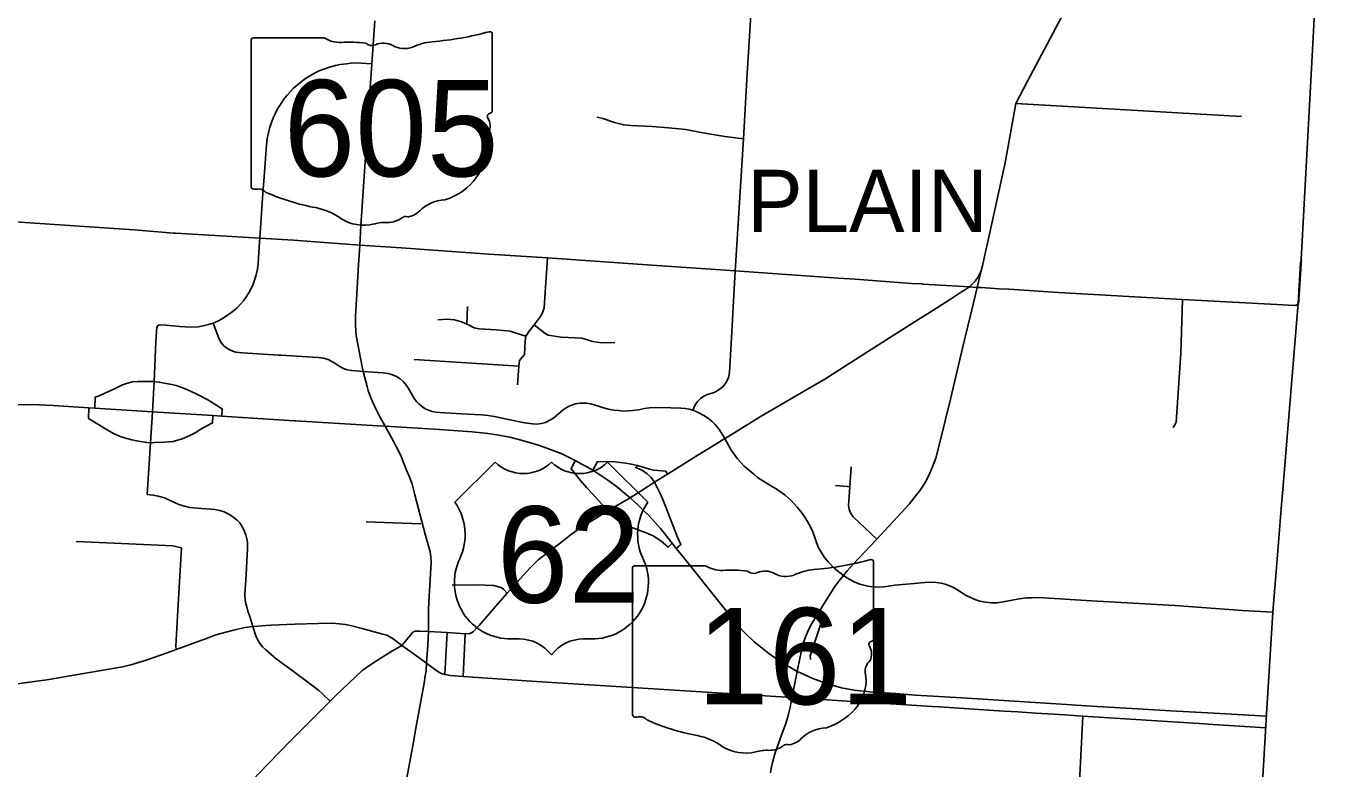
# Model space of a CAD drawing. Extents: x 1755200 to 1902939, y 644115 to 788070.
# Drawn here: x 1876290 to 1895161, y 756753 to 767475 of the extents above; entities that cross this region are included whole.
import ezdxf

# ---------------------------------------------------------------- set-up
doc = ezdxf.new("R2010")
doc.units = 0
for name, color, linetype in [('GM_X_City_Street', 7, 'Continuous'), ('GM_X_County', 7, 'Continuous'), ('GM_X_County_Road', 7, 'Continuous'), ('GM_X_Interchange_Ramps', 7, 'Continuous'), ('GM_X_State_Route', 7, 'Continuous'), ('GM_X_State_Shield', 7, 'Continuous'), ('GM_X_Township_Road', 7, 'Continuous'), ('GM_X_Township_Text', 7, 'Continuous'), ('GM_X_US_Route', 7, 'Continuous'), ('GM_X_US_Shield', 7, 'Continuous')]:
    doc.layers.add(name, color=color, linetype=linetype)

msp = doc.modelspace()

# ---------------------------------------------------------------- linework, layer by layer
at = {"layer": 'GM_X_City_Street'}
for points in [[(1879665, 764416), (1879710, 765065), (1879729, 765301), (1879750, 765625), (1879761, 765760), (1879771, 765853), (1879788, 765933), (1879805, 766001), (1879835, 766086), (1879859, 766149), (1879892, 766220), (1879921, 766279), (1879962, 766346), (1880013, 766422), (1880059, 766478), (1880153, 766579), (1880231, 766649), (1880311, 766710), (1880387, 766760), (1880463, 766799), (1880524, 766828), (1880587, 766854), (1880672, 766884), (1880760, 766907), (1880826, 766921), (1880916, 766932), (1880978, 766939), (1881052, 766943), (1881281, 766929)], [(1886648, 765849), (1886648, 765849), (1886705, 766792)], [(1884537, 766160), (1884616, 766141), (1884785, 766084), (1884921, 766050), (1885023, 766039), (1885329, 766028), (1885566, 766005), (1885815, 765982), (1886064, 765937), (1886381, 765880), (1886648, 765849)], [(1886535, 764015), (1886648, 765849)], [(1875732, 764675), (1875910, 764665), (1877850, 764535), (1878419, 764488), (1878447, 764486)], [(1878447, 764486), (1879014, 764455), (1879665, 764416), (1880151, 764384), (1881111, 764314)], [(1878163, 762916), (1878174, 763071), (1878179, 763120), (1878188, 763150), (1878212, 763161), (1878309, 763158), (1878510, 763141), (1878589, 763133), (1878681, 763130), (1878773, 763136), (1878847, 763151), (1878925, 763167), (1878990, 763189), (1879067, 763222), (1879152, 763267), (1879262, 763344), (1879339, 763408), (1879385, 763461), (1879429, 763511), (1879473, 763570), (1879511, 763634), (1879563, 763735), (1879595, 763822), (1879613, 763886), (1879631, 763969), (1879641, 764050), (1879661, 764362)], [(1879661, 764362), (1879665, 764416)], [(1881111, 764314), (1881704, 764273), (1882972, 764185), (1883819, 764131), (1885188, 764036), (1886531, 763943), (1888019, 763839), (1888260, 763821), (1888327, 763816)], [(1883388, 762296), (1883407, 762564), (1883413, 762646), (1883485, 762737), (1883495, 762929), (1883506, 763001), (1883554, 763074), (1883625, 763162), (1883727, 763297), (1883754, 763352), (1883770, 763410), (1883786, 763630), (1883819, 764131)], [(1885918, 761930), (1885950, 762007), (1885986, 762058), (1886028, 762100), (1886076, 762133), (1886132, 762158), (1886227, 762188), (1886285, 762218), (1886350, 762269), (1886400, 762333), (1886433, 762402), (1886448, 762475), (1886480, 763064), (1886531, 763943), (1886535, 764015)], [(1888317, 759797), (1888574, 760070), (1889041, 760575), (1889145, 760702), (1889193, 760763), (1889266, 760875), (1889320, 760977), (1889350, 761047), (1889381, 761113), (1889426, 761236), (1889486, 761464), (1889640, 762089), (1889813, 762827), (1889891, 763144), (1889947, 763382), (1890022, 763700)], [(1890022, 763700), (1890022, 763700), (1890087, 763700), (1890335, 763685)], [(1890335, 763685), (1890482, 763677), (1891197, 763632), (1892213, 763572)], [(1892853, 761682), (1892880, 761718), (1892897, 761759), (1892963, 762753), (1892991, 763528)], [(1882654, 763172), (1882663, 763430)], [(1878990, 763189), (1879042, 763047), (1879067, 762978), (1879088, 762936), (1879116, 762893), (1879150, 762856), (1879201, 762818), (1879242, 762796), (1879277, 762781), (1879318, 762769), (1879365, 762763), (1879414, 762760), (1879935, 762727), (1879968, 762725)], [(1882236, 763236), (1882368, 763246), (1882474, 763235), (1882575, 763205), (1882654, 763172), (1882679, 763162), (1882758, 763119), (1882834, 763104), (1883078, 763090), (1883282, 763071), (1883353, 763049), (1883506, 763001)], [(1883625, 763162), (1883787, 763038), (1883829, 763012), (1884019, 762985), (1884317, 762969), (1884364, 762956), (1884476, 762921), (1884598, 762901), (1884790, 762906)], [(1878138, 762343), (1878163, 762916)], [(1879968, 762725), (1880507, 762691), (1880546, 762687), (1880585, 762680), (1880617, 762671), (1880660, 762658), (1880686, 762644), (1880726, 762622), (1880821, 762562), (1880862, 762539), (1880895, 762525), (1880932, 762513), (1880992, 762502), (1881159, 762491), (1881448, 762470), (1881517, 762460), (1881579, 762441), (1881637, 762416), (1881691, 762384), (1881736, 762345), (1881784, 762289), (1881814, 762246), (1881846, 762184), (1881875, 762133), (1881905, 762086), (1881932, 762051), (1881967, 762016), (1882014, 761977), (1882053, 761952), (1882101, 761932), (1882156, 761912), (1882213, 761901), (1882265, 761897), (1882579, 761878), (1882864, 761862), (1882963, 761854), (1883055, 761839), (1883258, 761798), (1883492, 761750), (1883605, 761732), (1883665, 761731), (1883732, 761739), (1883790, 761755), (1883855, 761785), (1883904, 761815), (1883984, 761884), (1884044, 761934), (1884089, 761966), (1884134, 761989), (1884180, 762008), (1884230, 762021), (1884283, 762030), (1884345, 762034), (1884389, 762031), (1884440, 762024), (1884495, 762009), (1884599, 761974), (1884694, 761947), (1884775, 761933), (1884847, 761925), (1884906, 761919), (1884985, 761920), (1885053, 761926), (1885133, 761938), (1885222, 761954), (1885294, 761964), (1885381, 761969), (1885598, 761964), (1885747, 761960), (1885811, 761956), (1885864, 761946), (1885918, 761930), (1886007, 761891), (1886076, 761853), (1886131, 761820), (1886194, 761772), (1886242, 761724), (1886305, 761647), (1886379, 761520)], [(1881895, 762665), (1883407, 762564)], [(1878084, 761462), (1878113, 761906), (1878138, 762343)], [(1878036, 760713), (1878084, 761462)], [(1886379, 761520), (1886466, 761361), (1886562, 761229), (1886661, 761121), (1886797, 761005), (1886851, 760958), (1887030, 760848), (1887138, 760784), (1887251, 760702), (1887340, 760625), (1887427, 760531), (1887478, 760466), (1887525, 760400), (1887576, 760322), (1887620, 760238), (1887649, 760175), (1887729, 759955), (1887770, 759881), (1887821, 759805), (1887872, 759740), (1887966, 759647), (1888092, 759545)], [(1888203, 761114), (1888183, 760823), (1888168, 760556), (1888174, 760498), (1888194, 760449), (1888233, 760391), (1888574, 760070)], [(1879471, 759112), (1879464, 759135), (1879453, 759190), (1879449, 759274), (1879466, 759560), (1879487, 759936), (1879487, 760024), (1879479, 760075), (1879465, 760133), (1879436, 760206), (1879406, 760259), (1879375, 760304), (1879342, 760340), (1879295, 760379), (1879227, 760427), (1879150, 760462), (1879086, 760482), (1879013, 760497), (1878766, 760517), (1878651, 760525), (1878576, 760544), (1878493, 760570), (1878372, 760627), (1878288, 760665), (1878196, 760691), (1878125, 760704), (1878036, 760713)], [(1887979, 760842), (1888148, 760830), (1888183, 760823)], [(1881203, 760320), (1881991, 760292)], [(1877013, 760036), (1877343, 760021), (1877352, 760021)], [(1877352, 760021), (1878407, 759972), (1878533, 759946)], [(1878456, 758475), (1878452, 758525), (1878482, 759044), (1878533, 759946)], [(1887361, 757846), (1887425, 758159), (1887466, 758371), (1887505, 758547), (1887539, 758646), (1887573, 758725), (1887628, 758837), (1887717, 758980), (1887780, 759088), (1887969, 759385), (1888026, 759461), (1888092, 759545), (1888148, 759613), (1888239, 759714), (1888317, 759797)], [(1888092, 759545), (1888140, 759510), (1888249, 759452), (1888332, 759418), (1888447, 759389), (1888553, 759378), (1888679, 759379), (1888837, 759404), (1889005, 759421), (1889112, 759431), (1889269, 759442), (1889366, 759447), (1889438, 759445), (1889506, 759434), (1889561, 759420), (1889673, 759375), (1889731, 759344), (1889800, 759297), (1889857, 759261), (1889927, 759226), (1890003, 759195), (1890065, 759176), (1890146, 759159), (1890224, 759152), (1890312, 759152), (1890401, 759162), (1890529, 759188), (1890630, 759206), (1890741, 759220), (1890808, 759222), (1890902, 759225), (1890988, 759222), (1891674, 759179), (1892879, 759110), (1893855, 759041), (1894293, 759014)], [(1882444, 759407), (1882804, 759410), (1883040, 759399), (1883148, 759370), (1883183, 759346), (1883236, 759291)], [(1879562, 758807), (1879521, 758953), (1879494, 759029), (1879471, 759112)], [(1878931, 758651), (1879028, 758687), (1879287, 758754), (1879455, 758792), (1879562, 758807), (1879822, 758827), (1880172, 758844)], [(1880681, 757732), (1880558, 757847), (1880515, 757884), (1880434, 757947), (1880113, 758186), (1879902, 758343), (1879745, 758477), (1879703, 758515), (1879665, 758565), (1879629, 758622), (1879606, 758675), (1879562, 758807)], [(1880172, 758844), (1880174, 758844), (1880508, 758852), (1880708, 758856), (1880809, 758848), (1880903, 758837), (1880996, 758816), (1881142, 758779), (1881315, 758732)], [(1875399, 757881), (1875406, 757881), (1875693, 757917), (1876589, 758040), (1877681, 758226), (1877801, 758254), (1878022, 758324), (1878327, 758429), (1878456, 758475), (1878931, 758651)], [(1881315, 758732), (1881441, 758698), (1881497, 758682), (1881531, 758666), (1881589, 758628), (1881629, 758602), (1881691, 758555)], [(1882074, 758277), (1882074, 758277), (1882089, 758537), (1882099, 758734)], [(1882335, 758115), (1882371, 758720)], [(1882602, 758086), (1882630, 758704)], [(1881691, 758555), (1881716, 758535), (1881845, 758441), (1882074, 758277), (1882205, 758177), (1882276, 758134), (1882305, 758123), (1882335, 758115), (1882345, 758113)], [(1881920, 757341), (1882038, 757991), (1882054, 758096), (1882066, 758170), (1882074, 758277)], [(1882345, 758113), (1882389, 758104), (1882414, 758101), (1882602, 758086), (1883515, 758025)], [(1883515, 758025), (1883808, 758006), (1887349, 757783)], [(1887040, 756698), (1887049, 756760), (1887068, 756847), (1887103, 756969), (1887201, 757255), (1887260, 757407), (1887294, 757522), (1887322, 757641), (1887349, 757783), (1887361, 757846)], [(1887349, 757783), (1888438, 757713)], [(1888438, 757713), (1888853, 757687)], [(1888853, 757687), (1889372, 757654)], [(1889476, 757647), (1890410, 757587)], [(1890617, 757574), (1890669, 757571)], [(1890877, 757558), (1891292, 757531)], [(1881755, 756447), (1881874, 757087), (1881920, 757341)]]:
    msp.add_lwpolyline(points, dxfattribs=at)
at = {"layer": 'GM_X_County'}
msp.add_lwpolyline([(1895161, 772565), (1894704, 764108), (1894692, 764059), (1894658, 763478), (1894436, 760788), (1894418, 760567), (1894359, 759837), (1894293, 759014), (1894201, 757542), (1893595, 747153), (1893596, 747130), (1893480, 745419)], dxfattribs=at)
at = {"layer": 'GM_X_County_Road'}
for points in [[(1894613, 763444), (1894625, 763445), (1894638, 763449), (1894648, 763459), (1894657, 763468), (1894663, 763480), (1894667, 763496), (1894671, 763532), (1894702, 764044), (1894704, 764065), (1894710, 764091)], [(1890022, 763700), (1890077, 763927)], [(1888327, 763816), (1889078, 763761), (1889226, 763753)], [(1889226, 763753), (1889240, 763752), (1889913, 763712)], [(1889913, 763712), (1890022, 763700)], [(1892213, 763572), (1892299, 763566), (1892991, 763528), (1894351, 763455), (1894607, 763444), (1894613, 763444)], [(1887619, 758330), (1887615, 758344), (1887613, 758387), (1887777, 758876), (1887779, 758913), (1887771, 758938), (1887751, 758962), (1887717, 758980)], [(1889372, 757654), (1889476, 757647)], [(1890410, 757587), (1890617, 757574)], [(1890669, 757571), (1890877, 757558)], [(1890890, 747320), (1890890, 747323), (1890931, 747885), (1890949, 748370), (1890978, 749335), (1891096, 750643), (1891349, 754421), (1891423, 755633), (1891501, 756560), (1891551, 757514)], [(1891292, 757531), (1891551, 757514), (1893306, 757404), (1893425, 757394), (1893891, 757364)], [(1893891, 757364), (1894191, 757345)]]:
    msp.add_lwpolyline(points, dxfattribs=at)
at = {"layer": 'GM_X_Interchange_Ramps'}
for points in [[(1878138, 762343), (1878066, 762347), (1877903, 762344), (1877828, 762338), (1877739, 762316), (1877683, 762296), (1877556, 762236), (1877436, 762183), (1877347, 762139), (1877285, 762117), (1877284, 761959)], [(1879114, 761846), (1879119, 761952), (1878912, 762080), (1878774, 762152), (1878656, 762208), (1878551, 762252), (1878455, 762286), (1878392, 762303), (1878208, 762336), (1878138, 762343)], [(1877197, 761965), (1877193, 761811), (1877459, 761646), (1877551, 761596), (1877647, 761553), (1877746, 761521), (1877818, 761505), (1877911, 761482), (1878032, 761463), (1878084, 761462)], [(1878084, 761462), (1878144, 761464), (1878288, 761467), (1878415, 761480), (1878544, 761519), (1878652, 761564), (1878729, 761606), (1878811, 761657), (1878898, 761705), (1878982, 761748), (1878987, 761854)], [(1884220, 761207), (1884160, 761084), (1884202, 761029), (1884294, 760916), (1884389, 760808), (1884465, 760727), (1884647, 760528), (1884681, 760472)], [(1885553, 761009), (1885527, 761051), (1885412, 761058), (1885348, 761066), (1885290, 761081), (1885215, 761102), (1885117, 761134), (1885029, 761153), (1884951, 761167), (1884868, 761177), (1884790, 761183), (1884540, 761188), (1884472, 761066)], [(1885363, 760891), (1885318, 760961), (1885257, 761011), (1885191, 761058), (1885093, 761103), (1885117, 761134)], [(1885678, 759935), (1885745, 759990), (1885695, 760098), (1885484, 760640), (1885448, 760729), (1885383, 760855), (1885363, 760891)], [(1884681, 760472), (1884711, 760433), (1884765, 760394), (1884851, 760331), (1884936, 760283), (1885028, 760241), (1885245, 760161), (1885344, 760115), (1885456, 760044), (1885563, 759955), (1885618, 760010)]]:
    msp.add_lwpolyline(points, dxfattribs=at)
at = {"layer": 'GM_X_State_Route'}
for points in [[(1881111, 764314), (1881125, 764593), (1881150, 764948), (1881252, 766514), (1881281, 766929), (1881324, 767554)], [(1881087, 763959), (1881111, 764314)], [(1881057, 763452), (1881067, 763610), (1881086, 763947), (1881087, 763959)], [(1881475, 761698), (1881405, 761826), (1881342, 761950), (1881270, 762108), (1881231, 762216), (1881213, 762273), (1881159, 762491), (1881142, 762556), (1881057, 763011), (1881051, 763075), (1881045, 763164), (1881047, 763288), (1881057, 763452)], [(1874034, 761315), (1874400, 761488), (1874766, 761657), (1874922, 761724), (1875108, 761792), (1875262, 761840), (1875473, 761897), (1875610, 761930), (1875791, 761963), (1875997, 761991), (1876175, 762006), (1876381, 762012), (1876681, 761999), (1877197, 761965), (1877284, 761959), (1878113, 761906), (1878987, 761854), (1879114, 761846), (1880163, 761777)], [(1880163, 761777), (1880182, 761776), (1881370, 761704)], [(1881370, 761704), (1881475, 761698), (1882262, 761651), (1882733, 761619), (1882960, 761595), (1883087, 761577), (1883275, 761541), (1883458, 761495), (1883706, 761420), (1884019, 761304), (1884220, 761207), (1884472, 761066), (1884704, 760912), (1884834, 760815), (1884933, 760734)], [(1881904, 760707), (1881863, 760863), (1881831, 760952), (1881785, 761066), (1881696, 761287), (1881574, 761517), (1881475, 761698)], [(1882133, 759816), (1882127, 759886), (1882057, 760124), (1881904, 760707)], [(1884933, 760734), (1885012, 760668), (1885130, 760561), (1885221, 760466), (1885286, 760404), (1885452, 760222), (1885618, 760010), (1885678, 759935), (1885754, 759843), (1886364, 759080), (1886567, 758825), (1886685, 758701), (1886799, 758594), (1887014, 758420), (1887181, 758302), (1887425, 758159)], [(1882107, 759167), (1882118, 759401), (1882140, 759736), (1882133, 759816)], [(1882099, 758734), (1882101, 759040), (1882107, 759167)], [(1887425, 758159), (1887473, 758138)], [(1887473, 758138), (1887652, 758059), (1887835, 757991), (1888067, 757925), (1888249, 757891), (1888476, 757865), (1888849, 757839)], [(1888849, 757839), (1889133, 757819), (1889803, 757778), (1891315, 757680)], [(1891315, 757680), (1891524, 757667)], [(1891524, 757667), (1891758, 757652), (1892259, 757623)], [(1892259, 757623), (1892339, 757618), (1892821, 757591), (1893440, 757556), (1894201, 757515)]]:
    msp.add_lwpolyline(points, dxfattribs=at)
at = {"layer": 'GM_X_State_Shield'}
for p, q in [((1880593, 767307), (1879574, 767307)), ((1883020, 766254), (1883020, 767359)), ((1879540, 767270), (1879540, 765157)), ((1883020, 766254), (1883020, 766254)), ((1888529, 758633), (1888529, 759738)), ((1885049, 759650), (1885049, 757536)), ((1886102, 759686), (1885083, 759686)), ((1888529, 758633), (1888529, 758633))]:
    msp.add_line(p, q, dxfattribs=at)
for centre, major_axis, start_param, end_param in [((1879580, 767275), (40.3, 0), 1.712693, 3.28349), ((1880836, 767552), (391, 0), 4.042523, 4.731795), ((1881780, 770188), (3691, 0), 4.814394, 5.042369), ((1882982, 767364), (38.7, 0), 6.141152, 7.989035), ((1880966, 766120), (1404, 0), 1.404758, 1.657858), ((1881284, 767286), (113, 0), 3.836095, 5.185415), ((1881450, 767042), (235, 0), 0.950623, 2.079405), ((1881753, 767377), (282, 0), 4.081561, 5.145723), ((1882251, 766661), (743, 0), 1.699011, 2.107814), ((1883011, 766173), (60, 0), 1.883978, 3.671073), ((1882630, 766033), (360, 0), 5.934695, 6.695948), ((1882979, 766249), (41.5, 0), 5.05454, 6.418171), ((1883159, 765791), (262, 0), 2.387724, 3.262537), ((1881987, 765650), (923, 0), 5.101752, 6.440018), ((1879580, 765153), (40.7, 0), 3.00124, 4.508301), ((1879586, 765369), (310, 0), 4.665946, 4.897461), ((1879650, 765035), (112, 0), 0.519207, 1.627899), ((1881063, 766934), (2665, 0), 4.195997, 4.488961), ((1880268, 764208), (834, 0), 0.823519, 1.323587), ((1882376, 764564), (506, 0), 1.647645, 2.488434), ((1881170, 765025), (529, 0), 4.026481, 4.996735), ((1881476, 764294), (435, 0), 1.495662, 1.94098), ((1881515, 764867), (282, 0), 4.691044, 5.507374), ((1881770, 764662), (79.4, 0), 1.147584, 2.315152), ((1881736, 764952), (298, 0), 4.937069, 5.64225), ((1887289, 762567), (3691, 0), 4.814394, 5.042369), ((1888490, 759743), (38.7, 0), 6.141152, 7.989035), ((1885088, 759654), (40.3, 0), 1.712693, 3.28349), ((1886345, 759931), (391, 0), 4.042523, 4.731795), ((1886474, 758500), (1404, 0), 1.404758, 1.657858), ((1886793, 759665), (113, 0), 3.836095, 5.185415), ((1886959, 759421), (235, 0), 0.950623, 2.079405), ((1887262, 759756), (282, 0), 4.081561, 5.145723), ((1887760, 759041), (743, 0), 1.699011, 2.107814), ((1888520, 758552), (60, 0), 1.883978, 3.671073), ((1888488, 758629), (41.5, 0), 5.05454, 6.418171), ((1888139, 758412), (360, 0), 5.934695, 6.695948), ((1888668, 758170), (262, 0), 2.387724, 3.262537), ((1887496, 758030), (923, 0), 5.101752, 6.440018), ((1885089, 757532), (40.7, 0), 3.00124, 4.508301), ((1885095, 757748), (310, 0), 4.665946, 4.897461), ((1885158, 757415), (112, 0), 0.519207, 1.627899), ((1886572, 759313), (2665, 0), 4.195997, 4.488961), ((1887885, 756943), (506, 0), 1.647645, 2.488434), ((1885777, 756587), (834, 0), 0.823519, 1.323587), ((1887023, 757246), (282, 0), 4.691044, 5.507374), ((1887278, 757041), (79.4, 0), 1.147584, 2.315152), ((1887245, 757332), (298, 0), 4.937069, 5.64225), ((1886679, 757404), (529, 0), 4.026481, 4.996735), ((1886985, 756673), (435, 0), 1.495662, 1.94098)]:
    msp.add_ellipse(centre, major_axis=major_axis, ratio=0.8, start_param=start_param, end_param=end_param, dxfattribs=at)
at = {"layer": 'GM_X_Township_Road'}
for points in [[(1886705, 766792), (1886750, 767555), (1886850, 769340), (1886945, 770931), (1886981, 771591), (1887010, 772079), (1887174, 774834), (1887165, 774869), (1887135, 774898), (1887133, 774899)], [(1890584, 766357), (1893842, 766172)]]:
    msp.add_lwpolyline(points, dxfattribs=at)
at = {"layer": 'GM_X_US_Route'}
for points in [[(1890752, 766679), (1891033, 767215), (1891258, 767633), (1891448, 767988), (1891939, 768900), (1891995, 769008), (1892238, 769458), (1892242, 769476), (1892275, 769894), (1892301, 770323), (1892323, 770411), (1892348, 770477), (1892426, 770551), (1893210, 771367), (1893603, 771698), (1893929, 771992), (1893990, 772034), (1894050, 772066), (1894135, 772102), (1894659, 772333), (1894933, 772460), (1895161, 772565)], [(1890193, 764431), (1890430, 765504), (1890584, 766357), (1890752, 766679)], [(1889952, 763750), (1889996, 763794), (1890039, 763857), (1890077, 763927), (1890101, 764016), (1890121, 764104), (1890193, 764431)], [(1889344, 763348), (1889625, 763526), (1889799, 763638), (1889857, 763675), (1889913, 763712), (1889952, 763750)], [(1887539, 762214), (1887825, 762381), (1888335, 762706), (1889128, 763212), (1889344, 763348)], [(1886423, 761547), (1886907, 761844), (1887539, 762214)], [(1885944, 761252), (1886248, 761439)], [(1886248, 761439), (1886379, 761520), (1886423, 761547)], [(1885170, 760768), (1885363, 760891), (1885553, 761009), (1885915, 761235), (1885944, 761252)], [(1884075, 760070), (1884166, 760143), (1884326, 760252), (1884523, 760373), (1884681, 760472), (1885012, 760668), (1885170, 760768)], [(1883520, 759603), (1883562, 759650), (1883686, 759770), (1883963, 759981), (1884075, 760070)], [(1883070, 759098), (1883236, 759291), (1883520, 759603)], [(1882832, 758823), (1883070, 759098)], [(1881716, 758535), (1881856, 758704), (1881871, 758720), (1881884, 758730), (1881906, 758741), (1881972, 758742), (1882099, 758734), (1882371, 758720), (1882630, 758704), (1882699, 758706), (1882746, 758733), (1882810, 758797), (1882832, 758823)], [(1880757, 757805), (1881141, 758174), (1881205, 758217), (1881309, 758288), (1881557, 758441), (1881716, 758535)], [(1876171, 751557), (1876256, 751744), (1876325, 751910), (1876506, 752212), (1876807, 752667), (1876946, 752881), (1877196, 753260), (1877279, 753413), (1877324, 753507), (1877439, 753872), (1877494, 754090), (1877534, 754213), (1877567, 754283), (1877589, 754326), (1877657, 754437), (1878655, 755556), (1879084, 756067), (1879427, 756451), (1879564, 756594), (1879778, 756816), (1880124, 757173), (1880423, 757471), (1880681, 757732), (1880757, 757805)]]:
    msp.add_lwpolyline(points, dxfattribs=at)
at = {"layer": 'GM_X_US_Shield'}
for p, q in [((1883063, 761182), (1882483, 760601)), ((1885268, 760601), (1884688, 761182)), ((1883295, 758629), (1883411, 758629)), ((1884340, 758629), (1884456, 758629))]:
    msp.add_line(p, q, dxfattribs=at)
for centre, radius, start, end in [((1883470, 761596), 580, 225.573, 314.427), ((1884282, 761596), 580, 225.573, 314.427), ((1881818, 760136), 812, 334.5471, 35.0009), ((1885933, 760136), 812, 144.9991, 205.4529), ((1883286, 759441), 812, 154.8319, 270.6383), ((1884465, 759441), 812, 269.3617, 25.1681), ((1883411, 758049), 580, 36.8699, 90), ((1884340, 758049), 580, 90, 143.1301)]:
    msp.add_arc(centre, radius, start, end, dxfattribs=at)

# ---------------------------------------------------------------- texts
at = {"layer": 'GM_X_State_Shield'}
for s, p in [('605', (1880008, 765306)), ('161', (1885979, 757685))]:
    msp.add_text(s, height=1392.2, dxfattribs=at).set_placement(p)
at = {"layer": 'GM_X_Township_Text'}
msp.add_text('PLAIN', height=900, rotation=0, dxfattribs=at).set_placement((1886701, 764501))
at = {"layer": 'GM_X_US_Shield'}
msp.add_text('62', height=1392.2, dxfattribs=at).set_placement((1883087, 759151))

doc.saveas('drawing.dxf')
